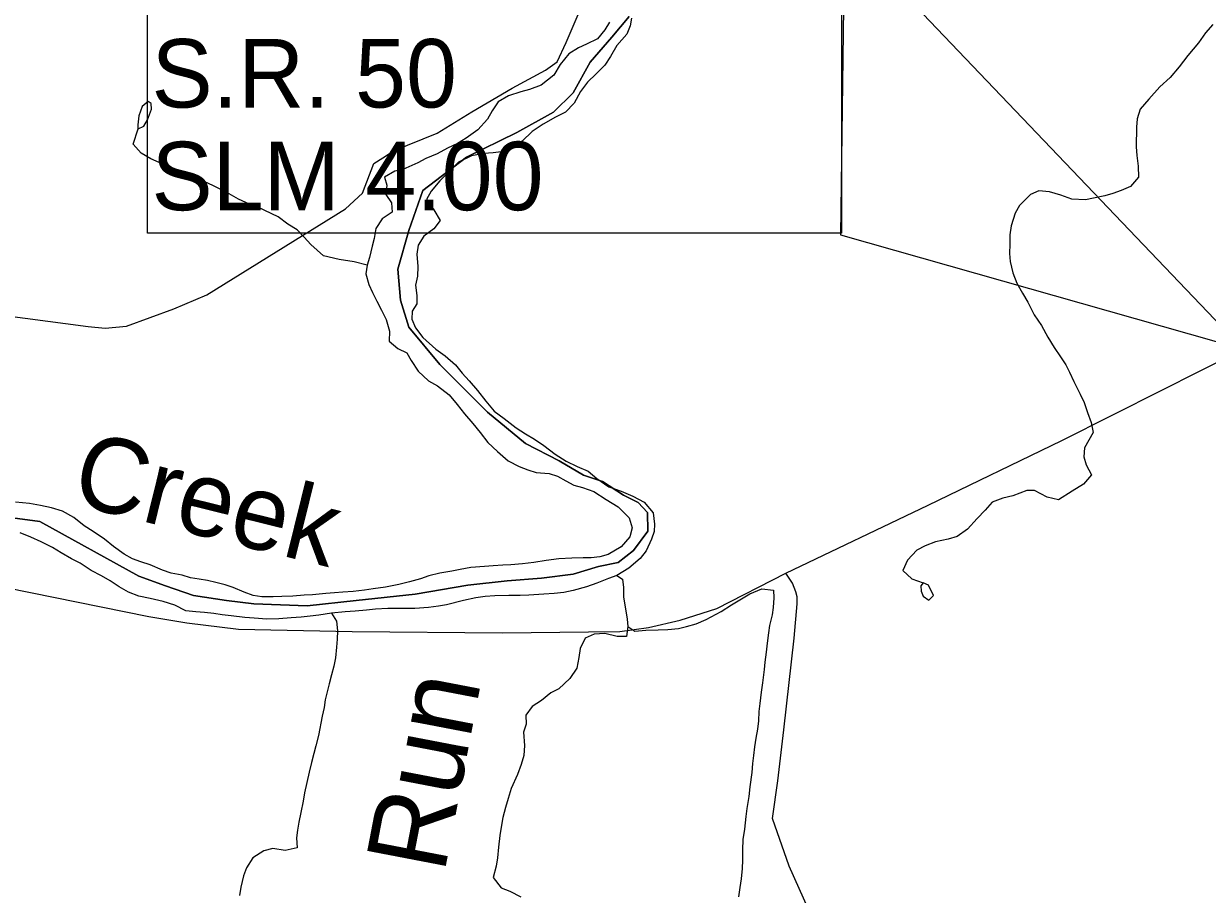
# Model space of a CAD drawing. Extents: x -139 to 835, y 0 to 440.
# Drawn here: x 414.36 to 462.76, y 270.35 to 305.95 of the extents above; entities that cross this region are included whole.
import ezdxf

# ---------------------------------------------------------------- set-up
doc = ezdxf.new("R2010")
doc.units = 0
for name, color, linetype in [('Default', 7, 'Continuous'), ('GM_X_County_Road', 7, 'Continuous'), ('GM_X_Major_River', 7, 'Continuous'), ('GM_X_Major_River_Text', 7, 'Continuous'), ('GM_X_Minor_Lake', 7, 'Continuous'), ('GM_X_Minor_River', 7, 'Continuous'), ('GM_X_Minor_River_Text', 7, 'Continuous'), ('GM_X_State_Route', 7, 'Continuous'), ('GM_X_US_Route', 7, 'Continuous'), ('SH_Text', 7, 'Continuous')]:
    doc.layers.add(name, color=color, linetype=linetype)

msp = doc.modelspace()

# ---------------------------------------------------------------- linework, layer by layer
at = {"layer": 'Default'}
for points in [[(413.07, 285.861), (415.021, 285.598), (419.067, 283.36), (420.157, 282.965), (421.305, 282.57), (422.653, 282.36), (423.773, 282.228), (425.953, 282.149), (427.962, 282.36), (430.372, 282.623), (432.524, 282.992), (434.13, 283.176), (435.536, 283.281), (436.828, 283.439), (437.861, 283.755), (438.664, 283.913), (439.295, 284.413), (439.884, 285.203), (439.869, 285.959), (439.488, 286.379), (438.893, 286.677), (438.033, 287.23), (437.258, 287.493), (436.254, 288.072), (434.877, 288.783), (433.327, 290.072), (431.376, 292.02), (430.114, 293.547), (429.769, 294.653), (429.654, 295.916), (430.114, 297.496), (430.687, 299.128), (432.466, 300.496), (434.532, 301.497), (436.024, 302.339), (436.828, 303.129), (437.527, 304.383), (438.412, 305.397), (439.118, 306.251)], [(439.118, 306.251), (438.412, 305.397), (437.527, 304.383), (436.828, 303.129), (436.024, 302.339), (434.532, 301.497), (432.466, 300.496), (430.687, 299.128), (430.114, 297.496), (429.654, 295.916), (429.769, 294.653), (430.114, 293.547), (431.376, 292.02), (433.327, 290.072), (434.877, 288.783), (436.254, 288.072), (437.258, 287.493), (438.033, 287.23), (438.893, 286.677), (439.488, 286.379), (439.869, 285.959), (439.884, 285.203), (439.295, 284.413), (438.664, 283.913), (437.861, 283.755), (436.828, 283.439), (435.536, 283.281), (434.13, 283.176), (432.524, 282.992), (430.372, 282.623), (427.962, 282.36), (425.953, 282.149), (423.773, 282.228), (422.653, 282.36), (421.305, 282.57), (420.157, 282.965), (419.067, 283.36), (415.021, 285.598), (413.07, 285.861)]]:
    msp.add_lwpolyline(points, dxfattribs=at)
at = {"layer": 'GM_X_County_Road'}
msp.add_lwpolyline([(411.116, 294.343), (416.995, 293.57), (417.691, 293.503), (418.565, 293.58), (420.5, 294.295), (421.856, 294.869), (427.525, 298.381), (428.221, 299.019), (428.673, 300.232), (429.043, 300.462), (429.487, 300.755), (431.27, 301.478), (432.683, 302.353), (434.337, 303.312), (435.703, 304.048), (436.18, 304.394), (436.542, 305.181), (437.762, 308.033), (439.074, 310.435), (440.22, 312.201), (440.91, 313.258), (441.831, 314.29), (442.373, 314.697), (442.839, 315.057)], dxfattribs=at)
at = {"layer": 'GM_X_Major_River'}
for points in [[(438.31, 306.017), (438.123, 305.707), (437.818, 305.338), (437.371, 305.116), (437.042, 304.963), (436.647, 304.716), (436.302, 304.288), (436.035, 303.847), (435.52, 303.444), (435.048, 303.258), (434.694, 303.166), (434.183, 303.004), (433.762, 302.757), (433.522, 302.387), (433.322, 302.054), (432.937, 301.614), (432.45, 301.272), (432.094, 301.048), (431.687, 300.86), (431.266, 300.637), (430.807, 300.439), (430.478, 300.262), (429.861, 299.993), (429.534, 299.925), (429.113, 299.678), (429.213, 299.353), (429.168, 298.97), (429.399, 298.631)], [(439.213, 306.175), (439.157, 305.863), (439.021, 305.529), (438.61, 305.066), (438.356, 304.612), (438.129, 304.255), (437.772, 303.899), (437.415, 303.567), (437.135, 303.186), (436.868, 302.709), (436.51, 302.329), (436.103, 302.13), (435.603, 301.848), (435.155, 301.541), (434.745, 301.149), (434.349, 300.842), (433.995, 300.726), (433.564, 300.671), (433.172, 300.639), (432.674, 300.549), (432.136, 300.291), (431.739, 299.888), (431.381, 299.52), (431.023, 299.104), (430.836, 298.758), (431.13, 298.335), (431.385, 297.9), (431.133, 297.567), (430.724, 297.26), (430.497, 296.89), (430.44, 296.531), (430.472, 296.027), (430.467, 295.631), (430.383, 295.26), (430.443, 294.839), (430.438, 294.503), (430.251, 294.193), (430.234, 293.869), (430.386, 293.52), (430.68, 293.12), (431.209, 292.646), (431.597, 292.366), (432.022, 292.001), (432.292, 291.662), (432.574, 291.347), (432.922, 290.959), (433.255, 290.523), (433.602, 290.111), (434.002, 289.806), (434.493, 289.429), (434.881, 289.184), (435.243, 288.964), (435.632, 288.708), (436.097, 288.354), (436.549, 288.061), (436.99, 287.84), (437.444, 287.655), (437.793, 287.351)], [(429.399, 298.631), (429.432, 298.247), (429.024, 297.975), (428.758, 297.582), (428.687, 297.175), (428.604, 296.852), (428.507, 296.397), (428.411, 296.075), (428.354, 295.727), (428.478, 295.282), (428.631, 294.956), (428.808, 294.606), (428.999, 294.244), (429.177, 293.858), (429.314, 293.376), (429.308, 292.968), (429.656, 292.676), (430.032, 292.492), (430.211, 292.178), (430.492, 291.743), (430.917, 291.342), (431.28, 291.145), (431.758, 290.78), (432.091, 290.38), (432.386, 290.005), (432.72, 289.605), (433.028, 289.229), (433.336, 288.83), (433.735, 288.453), (434.174, 288.076), (434.615, 287.843), (434.978, 287.707), (435.316, 287.595), (435.851, 287.553), (436.189, 287.453), (436.525, 287.257), (436.862, 287.086), (437.213, 286.986), (437.668, 286.824), (438.172, 286.495), (438.664, 286.189), (439.115, 285.74), (439.24, 285.331), (439.144, 284.972), (438.798, 284.556), (438.259, 284.25), (437.918, 284.146), (437.565, 284.114), (437.239, 284.106), (436.769, 284.099), (436.247, 284.069), (435.724, 284.003), (435.227, 283.925), (434.756, 283.87), (434.286, 283.827), (433.959, 283.807), (433.554, 283.788), (433.201, 283.756), (432.64, 283.714), (432.208, 283.635), (431.868, 283.567), (431.371, 283.477), (430.925, 283.374), (430.585, 283.258), (430.139, 283.131), (429.707, 283.016), (429.158, 282.915), (428.648, 282.837), (428.295, 282.793), (427.837, 282.738), (427.406, 282.707), (427.067, 282.675), (426.714, 282.655), (426.165, 282.602), (425.826, 282.582), (425.368, 282.539), (424.912, 282.533), (424.559, 282.513), (424.103, 282.518), (423.751, 282.57), (423.375, 282.707), (422.934, 282.892), (422.596, 283.004), (422.219, 283.105), (421.881, 283.181), (421.543, 283.233), (421.178, 283.297), (420.84, 283.397), (420.398, 283.486), (420.035, 283.611), (419.529, 283.821), (419.152, 283.945), (418.815, 284.069), (418.465, 284.254), (418.039, 284.571), (417.665, 284.875), (417.2, 285.193), (416.838, 285.425), (416.412, 285.754), (415.946, 286.024), (415.504, 286.15)], [(437.793, 287.351), (438.284, 287.009), (438.791, 286.836), (439.271, 286.638), (439.737, 286.393), (440.097, 285.957), (440.156, 285.488), (440.139, 285.188), (440.03, 284.878), (439.815, 284.4), (439.562, 284.079), (439.1, 283.688), (438.613, 283.382), (438.272, 283.266), (437.799, 283.079), (437.38, 282.928), (436.829, 282.778), (436.45, 282.687), (436.058, 282.655), (435.626, 282.624), (435.013, 282.583), (434.66, 282.575), (434.203, 282.568), (433.629, 282.563), (433.237, 282.531), (432.845, 282.476), (432.347, 282.362), (431.653, 282.19), (431.326, 282.134), (430.908, 282.078), (430.359, 282.037), (430.02, 282.041), (429.602, 282.034), (429.25, 282.038), (428.741, 282.008), (428.375, 281.976), (427.918, 281.933), (427.513, 281.902), (426.951, 281.849), (426.428, 281.771), (426.075, 281.727), (425.709, 281.683), (425.304, 281.652), (424.795, 281.61), (424.299, 281.604), (423.791, 281.646), (423.4, 281.675), (422.84, 281.741), (422.475, 281.782), (422.137, 281.834), (421.759, 281.874), (421.407, 281.902), (420.99, 281.943), (420.537, 282.177), (420.069, 282.326), (419.536, 282.441), (419.068, 282.542), (418.653, 282.704), (418.264, 282.924), (417.903, 283.169), (417.54, 283.377), (417.126, 283.598), (416.673, 283.891), (416.324, 284.076), (415.897, 284.309), (415.535, 284.529), (415.081, 284.763), (414.654, 284.96), (414.213, 285.134)], [(415.504, 286.15), (415.049, 286.251), (414.594, 286.329), (414.021, 286.384)]]:
    msp.add_lwpolyline(points, dxfattribs=at)
at = {"layer": 'GM_X_Minor_Lake'}
for points in [[(419.045, 301.647), (419.278, 301.762), (419.425, 302.025), (419.588, 302.455), (419.578, 302.683), (419.448, 302.768), (419.211, 302.567), (419.075, 302.185), (419.031, 301.813)], [(419.031, 301.813), (419.032, 301.675), (419.045, 301.647)], [(451.048, 282.966), (451.058, 282.75), (451.133, 282.545), (451.366, 282.374), (451.565, 282.576), (451.361, 282.986), (451.141, 283.085)], [(451.141, 283.085), (451.048, 282.966)]]:
    msp.add_lwpolyline(points, dxfattribs=at)
at = {"layer": 'GM_X_Minor_River'}
for points in [[(462.985, 305.923), (462.68, 305.578), (462.4, 305.173), (461.962, 304.65), (461.603, 304.186), (461.245, 303.746), (460.821, 303.366), (460.371, 302.867), (460.012, 302.463), (459.889, 302.057), (459.859, 301.721), (459.847, 300.917), (459.882, 300.556), (459.928, 300.124), (459.948, 299.68), (459.616, 299.299), (459.235, 299.136), (458.894, 299.007), (458.566, 298.915), (458.108, 298.824), (457.78, 298.744), (457.219, 298.774), (456.765, 298.947), (456.31, 299.072), (455.866, 299.113), (455.525, 298.973), (455.075, 298.522), (454.9, 298.199), (454.737, 297.685), (454.679, 297.314), (454.687, 296.942), (454.669, 296.558), (454.69, 296.222), (454.801, 295.764), (454.965, 295.343), (455.195, 294.932), (455.412, 294.57), (455.679, 294.051), (455.973, 293.615), (456.241, 293.132), (456.496, 292.71), (456.752, 292.335), (456.969, 292.008), (457.122, 291.706), (457.299, 291.321), (457.553, 290.802), (457.718, 290.464), (457.856, 290.054), (458.007, 289.645), (458.093, 289.236), (457.906, 288.926), (457.732, 288.604), (457.714, 288.244), (457.801, 287.907), (458.017, 287.508), (457.698, 287.128), (457.237, 286.833), (456.671, 286.479), (456.203, 286.593), (455.697, 286.862), (455.371, 286.866), (454.806, 286.644), (454.4, 286.553), (453.967, 286.389), (453.675, 286.057), (453.344, 285.712), (452.947, 285.285), (452.525, 284.989), (452.158, 284.873), (451.647, 284.759), (451.227, 284.596), (450.885, 284.42), (450.501, 284.016), (450.312, 283.586), (450.673, 283.246), (451.141, 283.085)], [(428.411, 296.075), (427.878, 296.213), (427.266, 296.316), (426.616, 296.455), (426.1, 296.917), (425.83, 297.221), (425.547, 297.524), (425.159, 297.757), (424.772, 298.049), (423.942, 298.443), (423.591, 298.567), (423.151, 298.776), (422.672, 299.046), (422.128, 299.328), (421.531, 299.599), (421.194, 299.748), (420.623, 299.982), (420.247, 300.107), (419.897, 300.279), (419.56, 300.427), (419.172, 300.66), (418.838, 301.024), (419.045, 301.647)], [(438.613, 283.382), (438.846, 283.235), (438.893, 282.899), (438.888, 282.515), (439.032, 281.601), (439.067, 281.301), (439.009, 280.893), (438.631, 280.898), (438.123, 281.012), (437.692, 280.993), (437.325, 280.829), (437.11, 280.399), (437.066, 280.028), (436.982, 279.597), (436.689, 279.18), (436.239, 278.753), (435.911, 278.589), (435.528, 278.282), (435.146, 278.034), (434.893, 277.677), (434.914, 277.305), (434.792, 276.982), (434.837, 276.442), (434.805, 276.022), (434.696, 275.663), (434.547, 275.257), (434.291, 274.684), (434.168, 274.265), (434.059, 273.907), (433.949, 273.488), (433.892, 273.177), (433.834, 272.758), (433.775, 272.278), (433.73, 271.847), (433.674, 271.499), (433.563, 271.033), (433.883, 270.621), (434.234, 270.473), (434.687, 270.252)], [(439.067, 281.301), (439.352, 281.118), (439.796, 281.149), (440.305, 281.167), (440.697, 281.174), (441.141, 281.217), (441.469, 281.298), (441.862, 281.413), (442.269, 281.588), (442.874, 281.918), (443.309, 282.189), (444.046, 282.636), (444.545, 282.847), (445.014, 282.793), (445.036, 282.481), (445.004, 282.086), (444.961, 281.786), (444.85, 281.343), (444.82, 281.044), (444.762, 280.624), (444.718, 280.253), (444.66, 279.846), (444.643, 279.546), (444.57, 278.995), (444.513, 278.623), (444.467, 278.156), (444.424, 277.832), (444.405, 277.449), (444.362, 277.101), (444.304, 276.742), (444.247, 276.382), (444.203, 276.023), (444.16, 275.699), (444.128, 275.328), (444.055, 274.741), (444.011, 274.357), (443.926, 273.866), (443.895, 273.531), (443.836, 273.015), (443.765, 272.596), (443.746, 272.164), (443.753, 271.744), (443.735, 271.409), (443.704, 270.989), (443.646, 270.63), (443.589, 270.246)], [(426.951, 281.849), (427.155, 281.522), (427.189, 281.126), (427.184, 280.79), (427.154, 280.454), (427.109, 280.023), (427.039, 279.676), (426.943, 279.329), (426.859, 278.958), (426.777, 278.635), (426.694, 278.3), (426.65, 277.989), (426.567, 277.63), (426.413, 276.84), (426.303, 276.421), (426.22, 276.11), (426.137, 275.739), (426.04, 275.344), (425.846, 274.506), (425.789, 274.159), (425.691, 273.692), (425.608, 273.297), (425.551, 272.974), (425.521, 272.663), (425.541, 272.254), (425.057, 272.14), (424.549, 272.218), (424.183, 272.126), (423.735, 271.844), (423.469, 271.439), (423.347, 271.104), (423.236, 270.638), (423.192, 270.302)]]:
    msp.add_lwpolyline(points, dxfattribs=at)
at = {"layer": 'GM_X_State_Route'}
msp.add_line((460.922, 290.981), (464.221, 292.642), dxfattribs=at)
for points in [[(445.522, 283.48), (451.343, 286.267), (456.813, 288.913), (460.922, 290.981)], [(446.478, 269.681), (445.666, 271.498), (444.974, 273.447), (445.201, 274.995), (445.436, 277.077), (445.865, 280.819), (445.993, 282.233), (445.993, 282.517), (445.939, 282.714), (445.79, 283.077), (445.522, 283.48)]]:
    msp.add_lwpolyline(points, dxfattribs=at)
at = {"layer": 'GM_X_US_Route'}
msp.add_line((460.922, 290.981), (464.221, 292.642), dxfattribs=at)
for points in [[(445.522, 283.48), (451.343, 286.267), (456.813, 288.913), (460.922, 290.981)], [(403.005, 285.05), (419.479, 281.708), (421.035, 281.452), (423.149, 281.197), (427.787, 281.102), (433.944, 281.045), (437.454, 281.084), (438.738, 281.103), (439.912, 281.262), (441.199, 281.555), (442.708, 282.036), (445.522, 283.48)]]:
    msp.add_lwpolyline(points, dxfattribs=at)
at = {"layer": 'SH_Text'}
for points in [[(447.801, 297.383), (419.429, 297.383), (419.429, 309.718), (447.801, 309.718)], [(464.221, 292.642), (447.929, 309.729), (447.761, 297.325)]]:
    msp.add_lwpolyline(points, close=True, dxfattribs=at)

# ---------------------------------------------------------------- texts
at = {"layer": 'GM_X_Major_River_Text'}
msp.add_text('Creek', height=3.0649, rotation=346.1215, dxfattribs=at).set_placement((416.222, 286.345))
at = {"layer": 'GM_X_Minor_River_Text'}
msp.add_text('Run', height=3.2702, rotation=79.1359, dxfattribs=at).set_placement((431.555, 271.159))
at = {"layer": 'SH_Text'}
for s, p in [('S.R. 50                ', (419.59, 302.524)), ('SLM 4.00           ', (419.59, 298.324))]:
    msp.add_text(s, height=2.79999, dxfattribs=at).set_placement(p)

doc.saveas('drawing.dxf')
